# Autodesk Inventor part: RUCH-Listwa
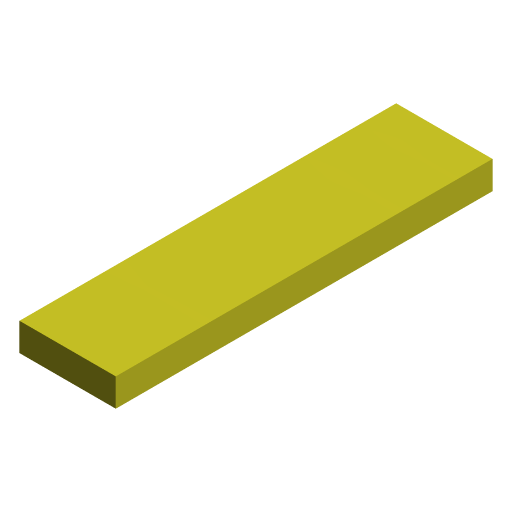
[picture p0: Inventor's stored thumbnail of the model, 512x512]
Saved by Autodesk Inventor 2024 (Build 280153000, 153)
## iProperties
Company: ATC
Created: 2023-03
Part Number: RUCH-Listwa
Document SubType Name: Modeling
Designer: Andrzej Jaskulski
Manufacturer: Standard
Standards Organization: Custom
Material: Kurs-AJ
Density: 1 g/cm^3
Appearance: Kanarkowa
Checked By: A.J.
Engr Approved By: Andrzej Jaskulski
Mfg Approved By: Andrzej Jaskulski
Authority: A.J.
Title: A.J.: Kurs R2024-MEP
Author: Andrzej Jaskulski
Revision Number: 1/24
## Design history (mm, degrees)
sketch "Szkic1"
  geometry: L1 (-12.745, -26.068)-(4.469, -26.068); L2 (4.469, -26.068)-(4.469, 41.26); L3 (4.469, 41.26)-(-12.745, 41.26); L4 (-12.745, 41.26)-(-12.745, -26.068)
  constraints: 8 end point, 2 parallel, 1 horizontal, 1 perpendicular
extrude "Wyciągnięcie proste1" new body sketch "Szkic1" distance "d0" = 5; taper "d1" = 0 deg
node "Bryła1"
node "Korpusy bryłowe"
node "Korpusy powierzchniowe"
